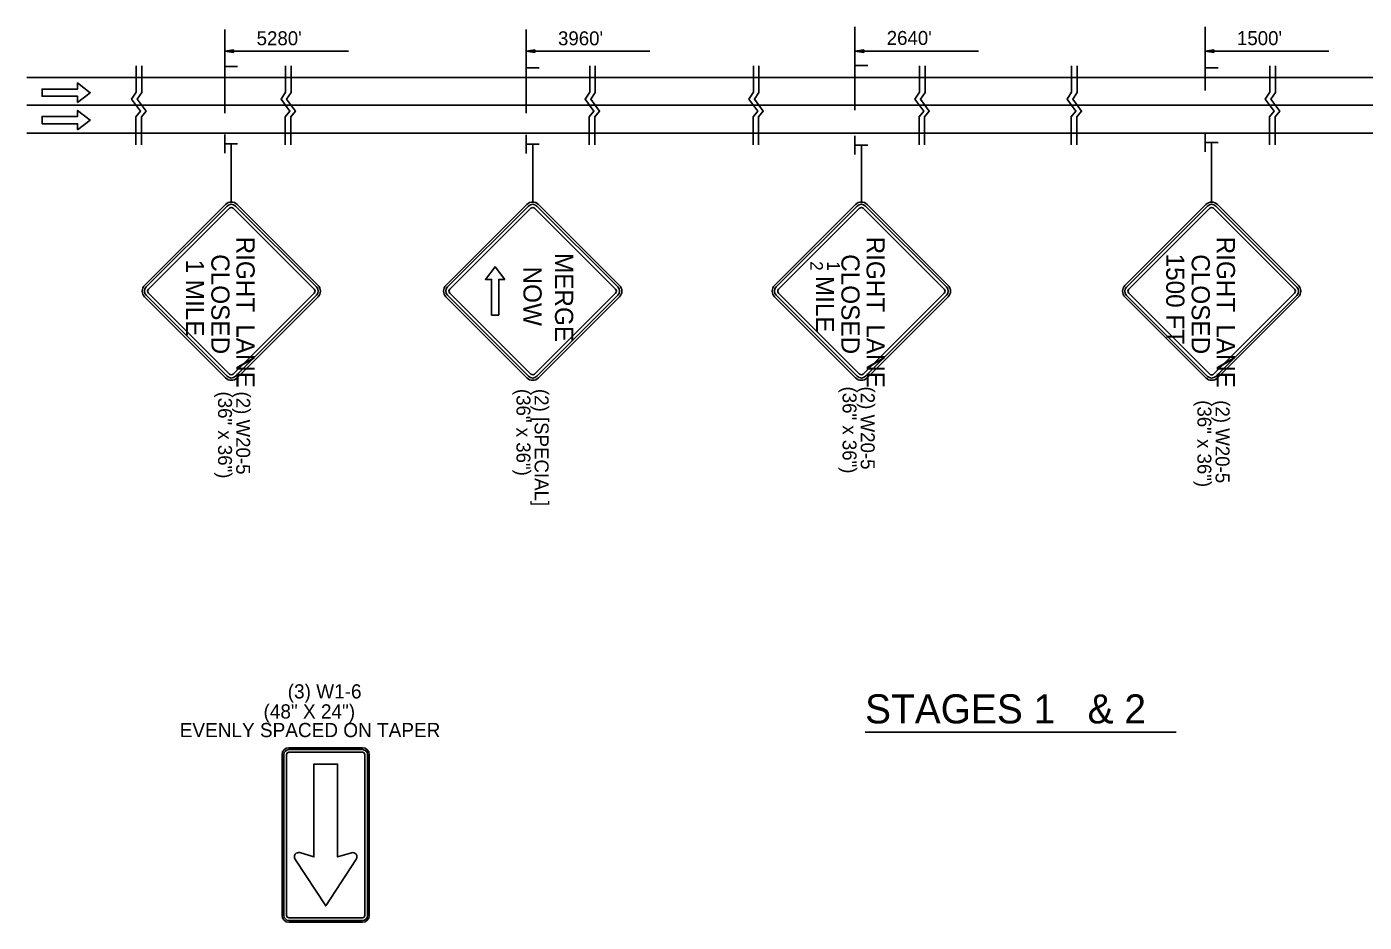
# Model space of a CAD drawing. Extents: x 1930579 to 1938222, y 596452 to 597559.
# Drawn here: x 1936684 to 1937236, y 597058 to 597428 of the extents above; entities that cross this region are included whole.
import ezdxf

# ---------------------------------------------------------------- set-up
doc = ezdxf.new("R2010")
doc.units = 0
for name, color, linetype in [('Default', 7, 'Continuous'), ('P_TC_Signs_Permanent', 7, 'Continuous'), ('P_TC_Signs_Temporary', 7, 'Continuous'), ('R_Border', 7, 'Continuous'), ('R_MOT', 7, 'Continuous'), ('R_Striping', 7, 'Continuous')]:
    doc.layers.add(name, color=color, linetype=linetype)

msp = doc.modelspace()

# ---------------------------------------------------------------- linework, layer by layer
at = {"layer": 'Default'}
for p, q in [((1936765.46, 597426.38), (1936765.46, 597391.9)), ((1936889.83, 597426.38), (1936889.83, 597391.9)), ((1937025.48, 597427.55), (1937025.48, 597393.08)), ((1937170.03, 597427.55), (1937170.03, 597401.26)), ((1936769.13, 597417.99), (1936765.46, 597417.44)), ((1936765.46, 597417.44), (1936816.56, 597417.44)), ((1936769.13, 597416.89), (1936765.46, 597417.44)), ((1936769.13, 597417.9), (1936766.08, 597417.44)), ((1936769.13, 597416.98), (1936766.08, 597417.44)), ((1936769.13, 597417.81), (1936766.71, 597417.44)), ((1936769.13, 597417.08), (1936766.71, 597417.44)), ((1936769.13, 597417.72), (1936767.32, 597417.44)), ((1936769.13, 597417.17), (1936767.32, 597417.44)), ((1936769.13, 597417.62), (1936767.94, 597417.44)), ((1936769.13, 597417.27), (1936767.94, 597417.44)), ((1936769.13, 597417.53), (1936768.55, 597417.44)), ((1936769.13, 597417.36), (1936768.55, 597417.44)), ((1936769.13, 597416.89), (1936769.13, 597417.99)), ((1936893.5, 597417.99), (1936889.83, 597417.44)), ((1936889.83, 597417.44), (1936940.93, 597417.44)), ((1936893.5, 597416.89), (1936889.83, 597417.44)), ((1936893.5, 597417.9), (1936890.44, 597417.44)), ((1936893.5, 597416.98), (1936890.44, 597417.44)), ((1936893.5, 597417.81), (1936891.08, 597417.44)), ((1936893.5, 597417.08), (1936891.08, 597417.44)), ((1936893.5, 597417.72), (1936891.69, 597417.44)), ((1936893.5, 597417.17), (1936891.69, 597417.44)), ((1936893.5, 597417.62), (1936892.31, 597417.44)), ((1936893.5, 597417.27), (1936892.31, 597417.44)), ((1936893.5, 597417.53), (1936892.92, 597417.44)), ((1936893.5, 597417.36), (1936892.92, 597417.44)), ((1936893.5, 597416.89), (1936893.5, 597417.99)), ((1937029.15, 597417.99), (1937025.48, 597417.44)), ((1937025.48, 597417.44), (1937076.58, 597417.44)), ((1937029.15, 597416.89), (1937025.48, 597417.44)), ((1937029.15, 597417.9), (1937026.09, 597417.44)), ((1937029.15, 597416.98), (1937026.09, 597417.44)), ((1937029.15, 597417.81), (1937026.73, 597417.44)), ((1937029.15, 597417.08), (1937026.73, 597417.44)), ((1937029.15, 597417.72), (1937027.34, 597417.44)), ((1937029.15, 597417.17), (1937027.34, 597417.44)), ((1937029.15, 597417.62), (1937027.96, 597417.44)), ((1937029.15, 597417.27), (1937027.96, 597417.44)), ((1937029.15, 597417.53), (1937028.57, 597417.44)), ((1937029.15, 597417.36), (1937028.57, 597417.44)), ((1937029.15, 597416.89), (1937029.15, 597417.99)), ((1937173.71, 597417.99), (1937170.03, 597417.44)), ((1937170.03, 597417.44), (1937221.14, 597417.44)), ((1937173.71, 597416.89), (1937170.03, 597417.44)), ((1937173.71, 597417.9), (1937170.65, 597417.44)), ((1937173.71, 597416.98), (1937170.65, 597417.44)), ((1937173.71, 597417.81), (1937171.28, 597417.44)), ((1937173.71, 597417.08), (1937171.28, 597417.44)), ((1937173.71, 597417.72), (1937171.89, 597417.44)), ((1937173.71, 597417.17), (1937171.89, 597417.44)), ((1937173.71, 597417.62), (1937172.51, 597417.44)), ((1937173.71, 597417.27), (1937172.51, 597417.44)), ((1937173.71, 597417.53), (1937173.13, 597417.44)), ((1937173.71, 597417.36), (1937173.13, 597417.44)), ((1937173.71, 597416.89), (1937173.71, 597417.99)), ((1936765.46, 597414.91), (1936765.46, 597407.25)), ((1936889.83, 597414.4), (1936889.83, 597406.74)), ((1937025.48, 597415.4), (1937025.48, 597407.74)), ((1937025.59, 597411.59), (1937030.82, 597411.59)), ((1937170.03, 597414.35), (1937170.03, 597406.69)), ((1937351.5, 597406.66), (1936683.76, 597406.66)), ((1936765.57, 597411.1), (1936770.8, 597411.1)), ((1936889.94, 597410.59), (1936895.17, 597410.59)), ((1937170.15, 597410.54), (1937175.38, 597410.54)), ((1937970.45, 597395.14), (1936683.76, 597395.14)), ((1937351.5, 597383.62), (1936683.76, 597383.62)), ((1936765.46, 597375.36), (1936765.46, 597383.02)), ((1936765.57, 597379.17), (1936770.8, 597379.17)), ((1936849.88, 597383.62), (1936917.44, 597383.62)), ((1936889.83, 597375.31), (1936889.83, 597382.97)), ((1936889.94, 597379.12), (1936895.17, 597379.12)), ((1937025.48, 597374.88), (1937025.48, 597382.54)), ((1937025.59, 597378.69), (1937030.82, 597378.69)), ((1937170.03, 597375.94), (1937170.03, 597383.6)), ((1937170.15, 597379.75), (1937175.38, 597379.75)), ((1937029.73, 597136.48), (1937158.05, 597136.48))]:
    msp.add_line(p, q, dxfattribs=at)
for points in [[(1936728.91, 597411.46), (1936728.91, 597400.51), (1936727.04, 597397.73), (1936730.69, 597392.74), (1936728.77, 597390.44), (1936728.76, 597378.82)], [(1936731.21, 597411.46), (1936731.21, 597400.41), (1936729.34, 597397.63), (1936732.99, 597392.65), (1936731.07, 597390.34), (1936731.07, 597378.82)], [(1936790.58, 597411.46), (1936790.58, 597400.51), (1936788.71, 597397.73), (1936792.36, 597392.74), (1936790.44, 597390.44), (1936790.44, 597378.82)], [(1936792.88, 597411.46), (1936792.88, 597400.41), (1936791.01, 597397.63), (1936794.66, 597392.65), (1936792.74, 597390.34), (1936792.74, 597378.82)], [(1936916.08, 597411.46), (1936916.08, 597400.51), (1936914.21, 597397.73), (1936917.85, 597392.74), (1936915.93, 597390.44), (1936915.93, 597378.82)], [(1936918.38, 597411.46), (1936918.38, 597400.41), (1936916.51, 597397.63), (1936920.15, 597392.65), (1936918.23, 597390.34), (1936918.23, 597378.82)], [(1936983.65, 597411.46), (1936983.65, 597400.51), (1936981.77, 597397.73), (1936985.42, 597392.74), (1936983.5, 597390.44), (1936983.5, 597378.82)], [(1936985.95, 597411.46), (1936985.95, 597400.41), (1936984.08, 597397.63), (1936987.72, 597392.65), (1936985.8, 597390.34), (1936985.8, 597378.82)], [(1937052.15, 597411.46), (1937052.15, 597400.51), (1937050.28, 597397.73), (1937053.93, 597392.74), (1937052.01, 597390.44), (1937052.01, 597378.82)], [(1937054.46, 597411.46), (1937054.46, 597400.41), (1937052.59, 597397.63), (1937056.23, 597392.65), (1937054.31, 597390.34), (1937054.31, 597378.82)], [(1937114.98, 597411.46), (1937114.98, 597400.51), (1937113.11, 597397.73), (1937116.75, 597392.74), (1937114.84, 597390.44), (1937114.83, 597378.82)], [(1937117.28, 597411.46), (1937117.28, 597400.41), (1937115.41, 597397.63), (1937119.06, 597392.65), (1937117.14, 597390.34), (1937117.13, 597378.82)], [(1937196.77, 597411.46), (1937196.77, 597400.51), (1937194.9, 597397.73), (1937198.54, 597392.74), (1937196.62, 597390.44), (1937196.62, 597378.82)], [(1937199.07, 597411.46), (1937199.07, 597400.41), (1937197.2, 597397.63), (1937200.84, 597392.65), (1937198.92, 597390.34), (1937198.92, 597378.82)]]:
    msp.add_lwpolyline(points, dxfattribs=at)
at = {"layer": 'P_TC_Signs_Permanent'}
for p, q in [((1936789.13, 597127.18), (1936789.13, 597060.81)), ((1936789.88, 597127.18), (1936789.88, 597060.81)), ((1936791.01, 597127.18), (1936791.01, 597060.81)), ((1936822.32, 597129.99), (1936791.95, 597129.99)), ((1936822.32, 597129.24), (1936791.95, 597129.24)), ((1936822.32, 597128.12), (1936791.95, 597128.12)), ((1936823.26, 597060.81), (1936823.26, 597127.18)), ((1936824.38, 597060.81), (1936824.38, 597127.18)), ((1936825.13, 597060.81), (1936825.13, 597127.18)), ((1936791.95, 597059.87), (1936822.32, 597059.87)), ((1936791.95, 597058.74), (1936822.32, 597058.74)), ((1936791.95, 597057.99), (1936822.32, 597057.99))]:
    msp.add_line(p, q, dxfattribs=at)
for points in [[(1936817.77, 597086.7), (1936812.01, 597084.98), (1936812.01, 597123.24), (1936802.26, 597123.24), (1936802.26, 597084.98), (1936796.51, 597086.73)], [(1936794.69, 597083.74), (1936807.13, 597064.74), (1936819.54, 597083.75)]]:
    msp.add_lwpolyline(points, dxfattribs=at)
for centre, radius, start, end in [((1936791.95, 597127.18), 2.81, 90, 180), ((1936791.95, 597127.18), 2.06, 90, 180), ((1936791.95, 597127.18), 0.938, 90, 180), ((1936822.32, 597127.18), 2.81, 360, 90), ((1936822.32, 597127.18), 2.06, 360, 90), ((1936822.32, 597127.18), 0.937, 360, 90), ((1936796.02, 597085), 1.8, 74.0309, 213.4755), ((1936818.25, 597085), 1.76, 326.5994, 105.9691), ((1936731.96, 597042.64), 75, 33.2286, 33.4755), ((1936882.34, 597042.74), 75, 146.5994, 146.857), ((1936791.95, 597060.81), 2.81, 180, 270), ((1936791.95, 597060.81), 2.06, 180, 270), ((1936791.95, 597060.81), 0.938, 180, 270), ((1936822.32, 597060.81), 2.81, 270, 360), ((1936822.32, 597060.81), 2.06, 270, 360), ((1936822.32, 597060.81), 0.938, 270, 360)]:
    msp.add_arc(centre, radius, start, end, dxfattribs=at)
at = {"layer": 'P_TC_Signs_Temporary'}
for p, q in [((1936732.39, 597320.83), (1936765.8, 597354.24)), ((1936733.05, 597320.16), (1936766.47, 597353.57)), ((1936733.98, 597319.23), (1936767.39, 597352.65)), ((1936768.98, 597352.65), (1936802.4, 597319.23)), ((1936769.91, 597353.57), (1936803.32, 597320.16)), ((1936770.58, 597354.24), (1936803.99, 597320.83)), ((1936856.76, 597320.83), (1936890.17, 597354.24)), ((1936857.42, 597320.16), (1936890.83, 597353.57)), ((1936858.35, 597319.23), (1936891.76, 597352.65)), ((1936893.35, 597352.65), (1936926.76, 597319.23)), ((1936894.28, 597353.57), (1936927.69, 597320.16)), ((1936894.94, 597354.24), (1936928.36, 597320.83)), ((1936992.41, 597320.83), (1937025.82, 597354.24)), ((1936993.07, 597320.16), (1937026.48, 597353.57)), ((1936994, 597319.23), (1937027.41, 597352.65)), ((1937029, 597352.65), (1937062.41, 597319.23)), ((1937029.93, 597353.57), (1937063.34, 597320.16)), ((1937030.59, 597354.24), (1937064.01, 597320.83)), ((1937136.97, 597320.8), (1937170.38, 597354.22)), ((1937137.63, 597320.14), (1937171.04, 597353.55)), ((1937138.56, 597319.21), (1937171.97, 597352.62)), ((1937173.56, 597352.62), (1937206.97, 597319.21)), ((1937174.49, 597353.55), (1937207.9, 597320.14)), ((1937175.15, 597354.22), (1937208.56, 597320.8)), ((1936765.8, 597282.64), (1936732.39, 597316.05)), ((1936766.47, 597283.3), (1936733.05, 597316.72)), ((1936767.39, 597284.23), (1936733.98, 597317.64)), ((1936802.4, 597317.64), (1936768.98, 597284.23)), ((1936803.32, 597316.72), (1936769.91, 597283.3)), ((1936803.99, 597316.05), (1936770.58, 597282.64)), ((1936890.17, 597282.64), (1936856.76, 597316.05)), ((1936890.83, 597283.3), (1936857.42, 597316.72)), ((1936891.76, 597284.23), (1936858.35, 597317.64)), ((1936926.76, 597317.64), (1936893.35, 597284.23)), ((1936927.69, 597316.72), (1936894.28, 597283.3)), ((1936928.36, 597316.05), (1936894.94, 597282.64)), ((1937025.82, 597282.64), (1936992.41, 597316.05)), ((1937026.48, 597283.3), (1936993.07, 597316.72)), ((1937027.41, 597284.23), (1936994, 597317.64)), ((1937062.41, 597317.64), (1937029, 597284.23)), ((1937063.34, 597316.72), (1937029.93, 597283.3)), ((1937064.01, 597316.05), (1937030.59, 597282.64)), ((1937170.38, 597282.62), (1937136.97, 597316.03)), ((1937171.04, 597283.28), (1937137.63, 597316.69)), ((1937171.97, 597284.21), (1937138.56, 597317.62)), ((1937206.97, 597317.62), (1937173.56, 597284.21)), ((1937207.9, 597316.69), (1937174.49, 597283.28)), ((1937208.56, 597316.03), (1937175.15, 597282.62))]:
    msp.add_line(p, q, dxfattribs=at)
for centre, radius, start, end in [((1936768.19, 597351.85), 3.37, 45, 135), ((1936768.19, 597351.85), 2.44, 45, 135), ((1936768.19, 597351.85), 1.12, 45, 135), ((1936892.56, 597351.85), 3.37, 45, 135), ((1936892.56, 597351.85), 2.44, 45, 135), ((1936892.56, 597351.85), 1.12, 45, 135), ((1937028.21, 597351.85), 3.37, 45, 135), ((1937028.21, 597351.85), 2.44, 45, 135), ((1937028.21, 597351.85), 1.12, 45, 135), ((1937172.76, 597351.83), 3.37, 45, 135), ((1937172.76, 597351.83), 2.44, 45, 135), ((1937172.76, 597351.83), 1.12, 45, 135), ((1936734.78, 597318.44), 3.37, 135, 225), ((1936734.78, 597318.44), 2.44, 135, 225), ((1936734.78, 597318.44), 1.13, 135, 225), ((1936801.6, 597318.44), 1.13, 315, 45), ((1936801.6, 597318.44), 2.44, 315, 45), ((1936801.6, 597318.44), 3.38, 315, 45), ((1936859.15, 597318.44), 3.37, 135, 225), ((1936859.15, 597318.44), 2.44, 135, 225), ((1936859.15, 597318.44), 1.13, 135, 225), ((1936925.97, 597318.44), 1.13, 315, 45), ((1936925.97, 597318.44), 2.44, 315, 45), ((1936925.97, 597318.44), 3.38, 315, 45), ((1936994.8, 597318.44), 3.37, 135, 225), ((1936994.8, 597318.44), 2.44, 135, 225), ((1936994.8, 597318.44), 1.13, 135, 225), ((1937061.62, 597318.44), 1.13, 315, 45), ((1937061.62, 597318.44), 2.44, 315, 45), ((1937061.62, 597318.44), 3.37, 315, 45), ((1937139.35, 597318.42), 3.37, 135, 225), ((1937139.35, 597318.42), 2.44, 135, 225), ((1937139.35, 597318.42), 1.13, 135, 225), ((1937206.17, 597318.42), 1.13, 315, 45), ((1937206.17, 597318.42), 2.44, 315, 45), ((1937206.17, 597318.42), 3.37, 315, 45), ((1936768.19, 597285.03), 3.38, 225, 315), ((1936768.19, 597285.03), 2.44, 225, 315), ((1936768.19, 597285.03), 1.12, 225, 315), ((1936892.56, 597285.03), 3.38, 225, 315), ((1936892.56, 597285.03), 2.44, 225, 315), ((1936892.56, 597285.03), 1.12, 225, 315), ((1937028.21, 597285.03), 3.37, 225, 315), ((1937028.21, 597285.03), 2.44, 225, 315), ((1937028.21, 597285.03), 1.12, 225, 315), ((1937172.76, 597285.01), 3.37, 225, 315), ((1937172.76, 597285.01), 2.44, 225, 315), ((1937172.76, 597285.01), 1.12, 225, 315)]:
    msp.add_arc(centre, radius, start, end, dxfattribs=at)
at = {"layer": 'R_Border'}
for p, q in [((1936768.19, 597379.17), (1936768.19, 597355.22)), ((1936892.56, 597379.12), (1936892.56, 597355.22)), ((1937028.21, 597378.69), (1937028.21, 597355.22)), ((1937172.76, 597379.75), (1937172.76, 597355.22))]:
    msp.add_line(p, q, dxfattribs=at)
at = {"layer": 'R_MOT'}
msp.add_lwpolyline([(1936881.06, 597323.31), (1936877.06, 597328.5), (1936873.06, 597323.31), (1936875.56, 597323.31), (1936875.56, 597308.59), (1936878.56, 597308.59), (1936878.56, 597323.31)], close=True, dxfattribs=at)
at = {"layer": 'R_Striping'}
for points in [[(1936704.77, 597396.34), (1936709.96, 597400.34), (1936704.77, 597404.34), (1936704.77, 597401.84), (1936690.06, 597401.84), (1936690.06, 597398.84), (1936704.77, 597398.84)], [(1936704.77, 597385.03), (1936709.96, 597389.03), (1936704.77, 597393.03), (1936704.77, 597390.53), (1936690.06, 597390.53), (1936690.06, 597387.53), (1936704.77, 597387.53)]]:
    msp.add_lwpolyline(points, close=True, dxfattribs=at)

# ---------------------------------------------------------------- texts
at = {"layer": 'Default'}
for s, height, p in [("5280'", 5.76, (1936778.63, 597419.92)), ("3960'", 5.76, (1936903, 597419.9)), ("2640'", 5.76, (1937038.65, 597420.05)), ("1500'", 5.76, (1937183.2, 597419.97)), ('STAGES 1   & 2', 12, (1937029.73, 597140.05))]:
    msp.add_text(s, height=height, rotation=360, dxfattribs=at).set_placement(p)
at = {"layer": 'P_TC_Signs_Temporary'}
for s, height, p in [('RIGHT\u2002LANE', 7.5, (1936770.32, 597340.96)), ('RIGHT\u2002LANE', 7.5, (1937030.33, 597340.96)), ('RIGHT\u2002LANE', 7.5, (1937174.89, 597340.94)), ('1 MILE', 7.5, (1936749.44, 597331.49)), ('CLOSED', 7.5, (1936759.94, 597333.69)), ('MERGE', 7.5, (1936901.77, 597334.2)), ('2', 5.25, (1937007.08, 597330.79)), ('1', 5.25, (1937014.08, 597330.79)), ('CLOSED', 7.5, (1937019.96, 597333.69)), ('1500 FT', 7.5, (1937154.01, 597333.94)), ('CLOSED', 7.5, (1937164.51, 597333.67)), ('NOW', 7.5, (1936888.75, 597328.6)), (' MILE', 7.5, (1937009.46, 597327.53))]:
    msp.add_text(s, height=height, rotation=270, dxfattribs=at).set_placement(p)
at = {"layer": 'R_Border'}
for s, height, rotation, p in [('(36" x 36")', 5.76, 270, (1936762.71, 597277.02)), ('(2) W20-5', 5.76, 270, (1936770.2, 597277.02)), ('(36" x 36")', 5.76, 270, (1936885.87, 597278.09)), ('(2) [SPECIAL]', 5.76, 270, (1936893.36, 597278.09)), ('(36" x 36")', 5.76, 270, (1937020.45, 597279.07)), ('(2) W20-5', 5.76, 270, (1937027.94, 597279.07)), ('(36" x 36")', 5.76, 270, (1937166.88, 597273.43)), ('(2) W20-5', 5.76, 270, (1937174.37, 597273.43)), ('(3) W1-6', 5.859, 0.0075, (1936791.46, 597150.34)), ('(48" X 24")', 5.8594, 0.0075, (1936781.48, 597142.07)), ('EVENLY SPACED ON TAPER', 5.8594, 0.0075, (1936746.9, 597134.38))]:
    msp.add_text(s, height=height, rotation=rotation, dxfattribs=at).set_placement(p)

doc.saveas('drawing.dxf')
